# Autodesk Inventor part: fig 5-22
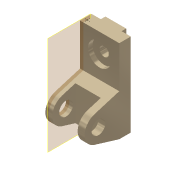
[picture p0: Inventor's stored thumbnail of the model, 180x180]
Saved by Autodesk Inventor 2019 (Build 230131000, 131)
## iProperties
Shininess: 65.0
Angle Display Precision: 2
Document Length Units: 11269
Document Angle Units: 11279
Document Time Units: 11290
Document Mass Units: 11283
Document Length Units Precision: 3
Document Angle Units Precision: 2
Compacted: False
Created: 2001-11
Part Number: fig 5-22
Document SubType Name: Modeling
Designer: Renu Muthoo
Density: 1 g/cm^3
Material: Generic
Appearance: Metal-Titanium (Polished)
Density: 0.0
Volumn: 0.0
Area: 0.0
PropertySet Name: Model Information
Control State: 0
Master: False
Checked Out: False
Author: Renu Muthoo
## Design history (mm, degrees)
node "Sketch1"
sketch "Sketch2"
  geometry: L1 (33.257, 104.664)-(33.257, -75.336); L2 (33.257, -75.336)-(8.257, -75.336); L3 (8.257, -75.336)-(-45.451, -59.045); L4 (-45.451, -1.628)-(8.257, 14.664); L5 (8.257, 14.664)-(8.257, 104.664); L6 (8.257, 104.664)-(33.257, 104.664); C1 r 15 at (-36.743, -30.336); A1 r 30 centre (-36.743, -30.336) between (-45.451, -1.628) and (-45.451, -59.045)
  constraints: 12 end point, 2 centre point, 2 equal length, 2 parallel, 2 point on circle, 2 tangent, 1 coincident, 1 perpendicular, 1 vertical
  dimensions: "d0" = 180 distance of L1.start L1.end; "d1" = 30 radius of A1; "d2" = 25 distance of L5.end L1.start; "d3" = 45 distance from line of L2 A1.centre; "d4" = 70 distance from line of L1 A1.centre; "d5" = 30 diameter of C1
extrude "Extrusion1" new body sketch "Sketch2" distance "d6" = 85; taper "d7" = 0 deg
workplane "Work Plane1"
sketch "Sketch3"
  geometry: L1 (15, 62.364)-(70, 62.364); L2 (70, 62.364)-(70, -52.386); L3 (70, -52.386)-(15, -52.386); L4 (15, -52.386)-(15, 62.364); L5 (0, -45)-(0, -28.708) reference
  constraints: 8 end point, 2 parallel, 1 horizontal, 1 perpendicular
  dimensions: "d8" = 55 distance of L1.start L1.end; "d9" = 15 distance between parallel lines of L5 L4
extrude "Extrusion2" cut sketch "Sketch3" distance "d10" = 50; taper "d11" = 0 deg
sketch "Sketch4"
  geometry: L1 (0, 25)-(85, 25) reference; L2 (0, 0)-(0, 25) reference; L3 (20, 25)-(65, 25); L4 (65, 25)-(65, 35); L5 (65, 35)-(20, 35); L6 (20, 35)-(20, 25)
  constraints: 8 end point, 2 parallel, 1 horizontal, 1 perpendicular, 1 point on line
  dimensions: "d12" = 45 distance of L4.end L5.end; "d13" = 10 distance of L3.end L4.end; "d14" = 20 distance between parallel lines of L2 L6
extrude "Extrusion3" join sketch "Sketch4" stored distance "d15" = 50; taper "d16" = 0 deg
sketch "Sketch5"
  geometry: L1 (85, 0)-(85, 90) reference; L2 (0, 90)-(85, 90) reference; 1 further point
  dimensions: "d17" = 42 distance from line of L2 point (42.5, 48); "d18" = 42.5 distance from line of L1 point (42.5, 48)
hole "Hole1" sketch "Sketch5" at (42.5, 48) diameter "d19" = 20; stored, may be unused: countersink angle "d23" = 82 deg, drill point angle "d25" = 118 deg; dims "d20" = 6, "d21" = 50, "d22" = 10, "d24" = 8
sketch "Sketch11"
  geometry: 1 further point
workplane "Work Plane17"
body "Solid1"
